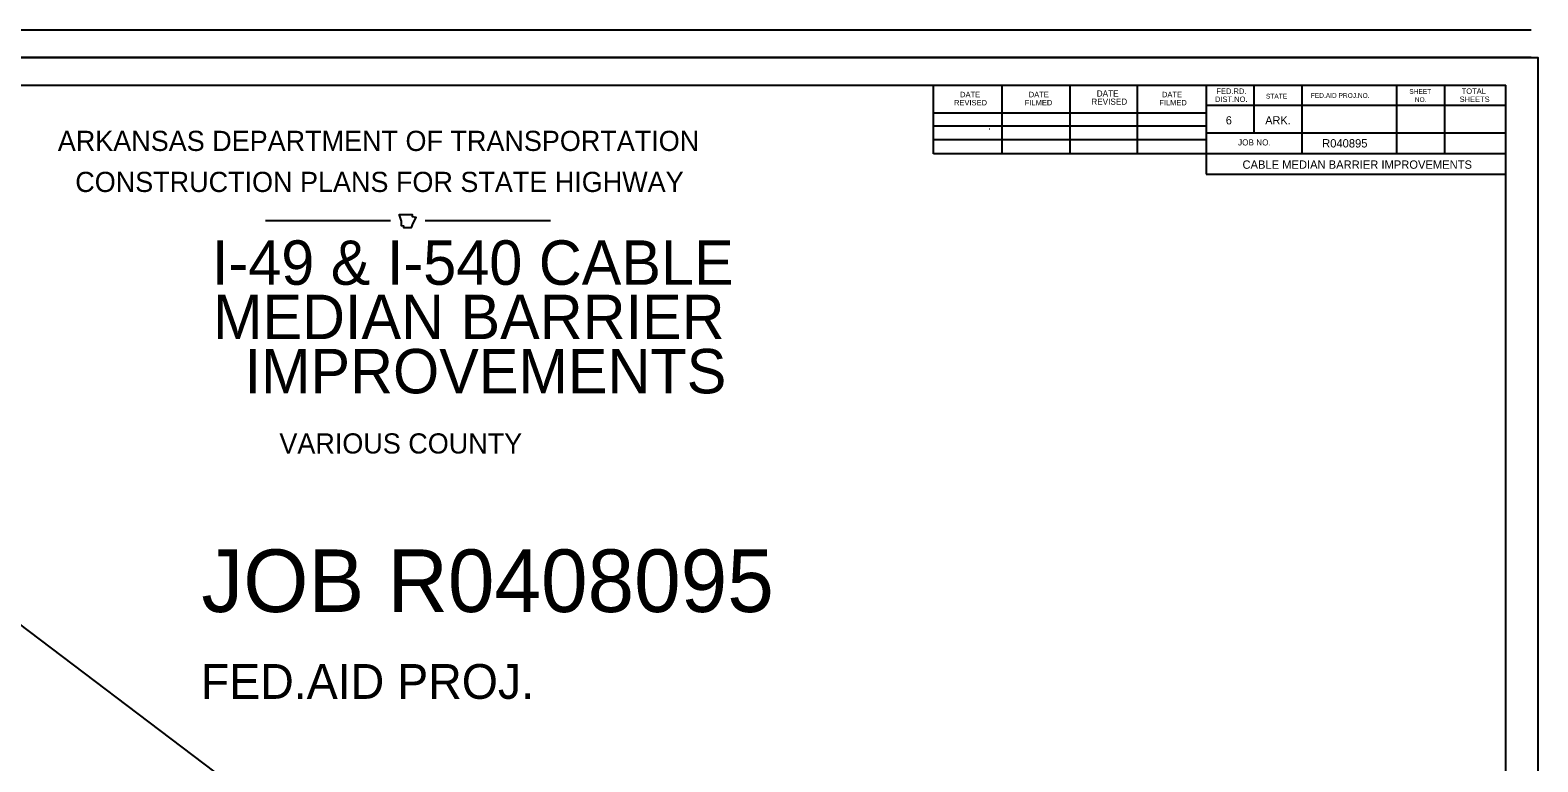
# Model space of a CAD drawing. Extents: x 21307 to 29830, y 1322443 to 1332359.
# Drawn here: x 24924 to 27092, y 1326530 to 1327582 of the extents above; entities that cross this region are included whole.
import ezdxf

# ---------------------------------------------------------------- set-up
doc = ezdxf.new("R2010")
doc.units = 0
doc.layers.add('R_Draft', color=7, linetype='Continuous')
doc.layers.add('R_No Plot', color=7, linetype='Continuous')

msp = doc.modelspace()

# ---------------------------------------------------------------- linework, layer by layer
at = {"layer": 'R_Draft'}
for p, q in [((27081.9, 1327581.7), (23572.1, 1327581.7)), ((27081.9, 1327542.3), (23808.3, 1327542.3)), ((23883.9, 1327502.8), (27045.7, 1327502.8)), ((26223, 1327404.1), (26223, 1327502.8)), ((26321.7, 1327404.1), (26321.7, 1327500.9)), ((26419.4, 1327404.1), (26419.4, 1327500.9)), ((26516.1, 1327404.1), (26516.1, 1327500.9)), ((26614.8, 1327502.8), (26614.8, 1327374.8)), ((26683.2, 1327502.8), (26683.2, 1327433.5)), ((26752.6, 1327502.8), (26752.6, 1327404.1)), ((26888.4, 1327502.8), (26888.4, 1327404.1)), ((26957.7, 1327502.8), (26957.7, 1327404.1)), ((27045.7, 1325448.4), (27045.7, 1327502.8)), ((26223, 1327462.8), (26614.8, 1327462.8)), ((27045.7, 1327473.5), (26614.8, 1327473.5)), ((27045.7, 1327473.8), (27045.7, 1327473.8)), ((26223, 1327444.2), (26614.8, 1327444.2)), ((26303.9, 1327439.3), (26303.2, 1327439.3)), ((27045.7, 1327433.5), (26614.8, 1327433.5)), ((26223, 1327404.1), (26223, 1327424.7)), ((26223, 1327424.7), (26614.8, 1327424.7)), ((27045.7, 1327404.1), (26223, 1327404.1)), ((26614.8, 1327374.8), (27045.7, 1327374.8)), ((25262.1, 1327308), (25442.1, 1327308)), ((25492.1, 1327308), (25672.1, 1327308))]:
    msp.add_line(p, q, dxfattribs=at)
msp.add_lwpolyline([(25453.8, 1327317.1), (25457.6, 1327307.1), (25457.6, 1327301), (25460.7, 1327300.3), (25460.7, 1327298), (25472.1, 1327298), (25474.4, 1327304.1), (25479, 1327312.5), (25473.6, 1327313.2), (25473.6, 1327316.3), (25454.6, 1327316.3)], dxfattribs=at)
at = {"layer": 'R_No Plot'}
msp.add_line((23883.9, 1327502.8), (25205.3, 1326503), dxfattribs=at)
msp.add_lwpolyline([(23808.3, 1327542.3), (27091.7, 1327542.3), (27091.7, 1325409), (23808.3, 1325409)], close=True, dxfattribs=at)

# ---------------------------------------------------------------- texts
at = {"layer": 'R_Draft'}
for s, height, p in [('FED.RD.', 7.82, (26629.5, 1327490.1)), ('SHEET', 6.84, (26906.9, 1327490.1)), ('TOTAL', 7.82, (26982.2, 1327490.1)), ('REVISED', 7.82, (26252.3, 1327473.5)), ('DATE', 7.82, (26261.1, 1327485.2)), ('FILMED', 7.82, (26354, 1327473.5)), ('DATE', 7.82, (26359.8, 1327485.2)), ('REVISED', 8.79, (26449.7, 1327474.5)), ('DATE', 8.79, (26457.5, 1327486.2)), ('FILMED', 7.82, (26547.4, 1327473.5)), ('DATE', 7.82, (26551.3, 1327485.2)), ('DIST.NO.', 7.82, (26627.5, 1327478.4)), ('STATE', 6.84, (26700.8, 1327483.3)), ('FED.AID PROJ.NO.', 6.841, (26765.3, 1327484.3)), ('NO.', 6.84, (26914.8, 1327478.4)), ('SHEETS', 7.82, (26979.2, 1327478.4)), ('6', 11.7, (26643.1, 1327446.2)), ('ARK.', 11.72, (26699.8, 1327446.2)), ('ARKANSAS DEPARTMENT OF TRANSPORTATION ', 29, (24963.7, 1327408)), ('JOB NO.', 8.79, (26660.7, 1327415.9)), ('R040895', 12, (26781.6, 1327413)), ('CABLE MEDIAN BARRIER IMPROVEMENTS', 12, (26667.1, 1327382.4)), ('CONSTRUCTION PLANS FOR STATE HIGHWAY', 29, (24988.8, 1327349)), ('I-49 & I-540 CABLE ', 63.871, (25185.3, 1327215.6)), ('MEDIAN BARRIER ', 63.871, (25186.8, 1327137.5)), ('IMPROVEMENTS', 63.871, (25232.1, 1327059.5)), ('VARIOUS COUNTY', 29, (25282.3, 1326973)), ('JOB R0408095', 90, (25170.2, 1326745.1)), ('FED.AID PROJ. ', 50, (25169.3, 1326620.3))]:
    msp.add_text(s, height=height, dxfattribs=at).set_placement(p)

doc.saveas('drawing.dxf')
